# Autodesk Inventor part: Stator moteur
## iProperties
Created: 2002-05
Part Number: Stator moteur
Material: Par défaut
Document SubType Name: Modélisation
Designer: Flavien MARTY
Control State: 0
Master: False
Checked Out: False
Shininess: 20.0
Length Units: 11269
Angle Units: 11279
Time Units: 11290
Mass Units: 11283
Length Display Precision: 3
Angle Display Precision: 2
Compacted: True
Density: 0.0
Volumn: 0.0
Area: 0.0
PropertySet Name: Model Information
Author: Flavien MARTY
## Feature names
1. Extrusion1
2. Congé1 [Fillet]
3. Extrusion2
4. Chanfrein1 [Chamfer]
